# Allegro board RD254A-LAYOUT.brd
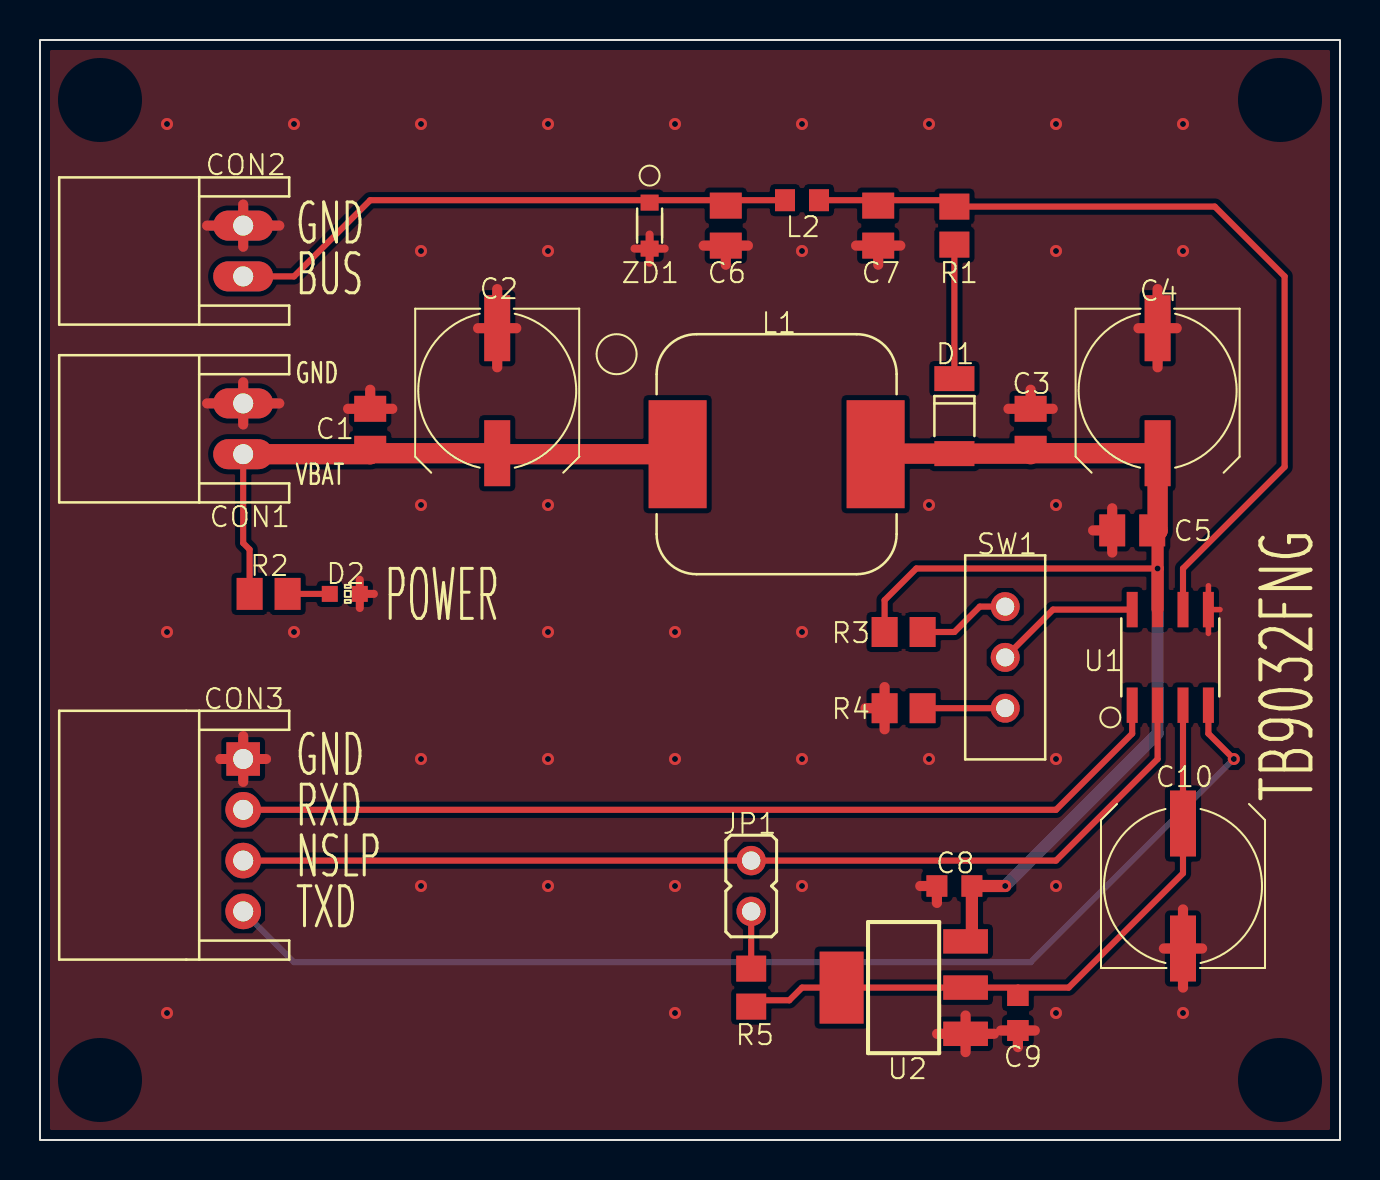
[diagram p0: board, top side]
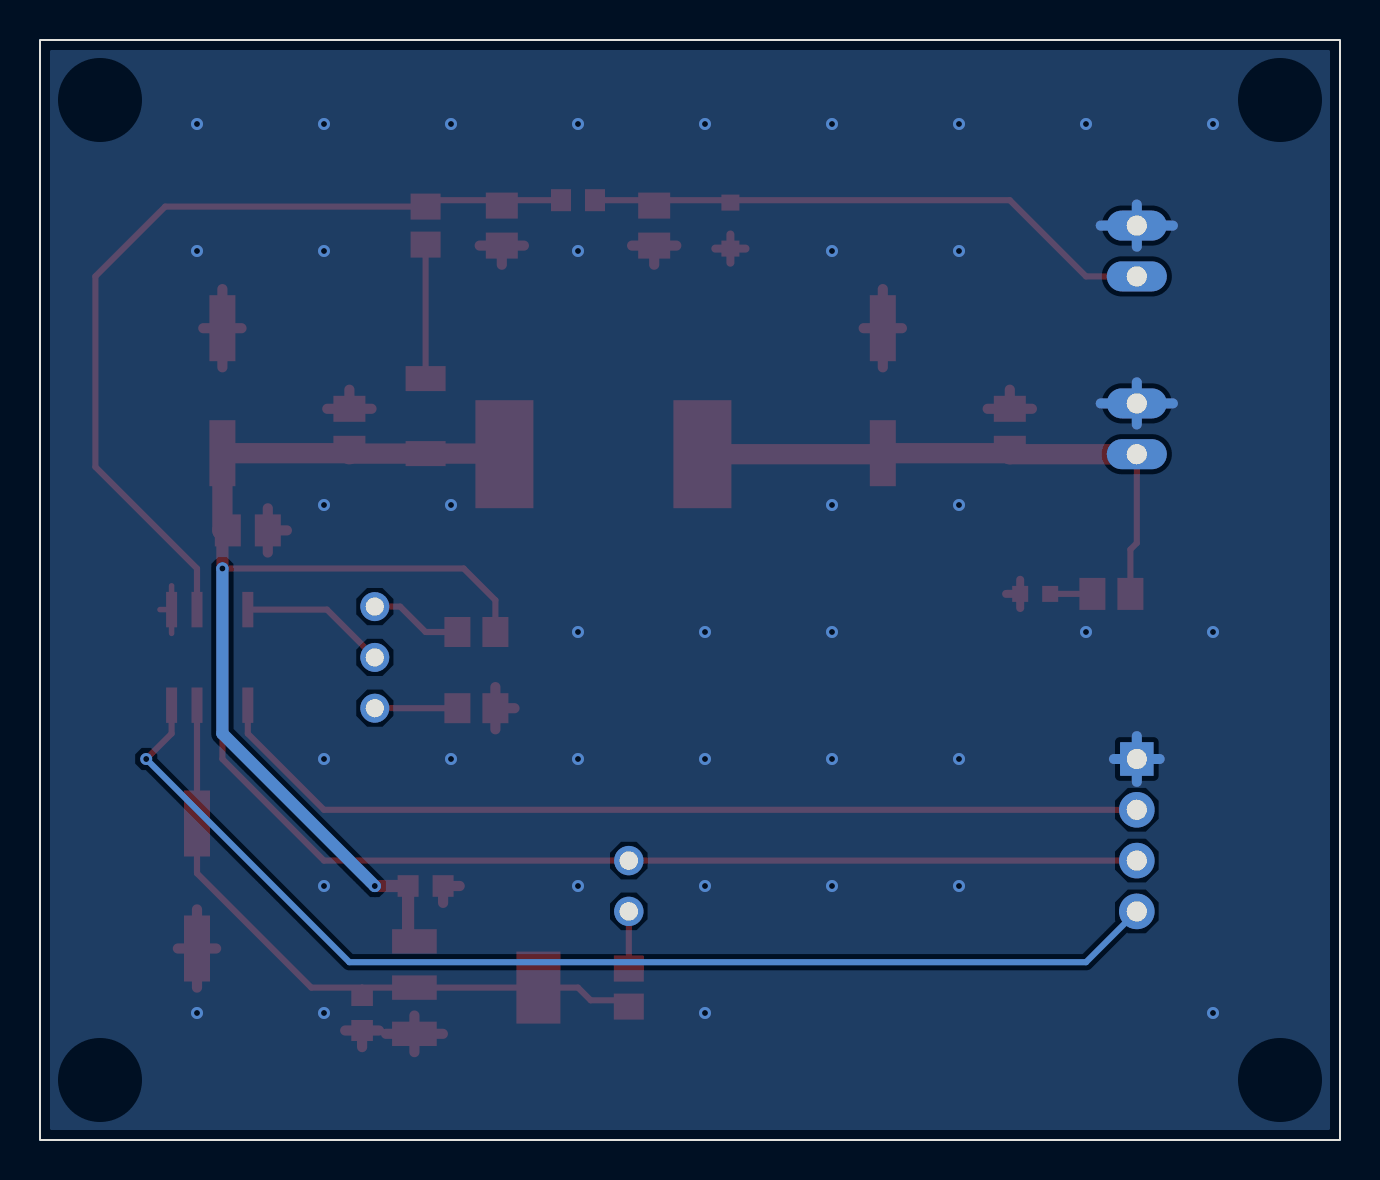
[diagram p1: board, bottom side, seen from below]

Outline 65 x 55 mm; copper layers: TOP, BOTTOM. Coordinates in mm from the lower left corner of the outline.
Outline path: rectangle 0,0 65,55

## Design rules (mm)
constraint set DEFAULT: 

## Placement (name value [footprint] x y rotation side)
C1  -  [C0805K]  16.51 35.56 90 top
C2  -  [UD_8X10_NICHICON_01]  22.86 37.47 270 top
C3  -  [C0805K]  49.53 35.56 90 top
C4  -  [UD_8X10_NICHICON_01]  55.88 37.47 270 top
C5  -  [C0805K]  54.61 30.48 180 top
C6  -  [C0805K]  34.29 45.72 270 top
C7  -  [C0805K]  41.91 45.72 270 top
C8  -  [C0603K]  45.72 12.7 0 top
C9  -  [C0603K]  48.9 6.35 90 top
C10  -  [UD_8X10_NICHICON_01]  57.15 12.7 90 top
CON1  -  [S2B_XH_A]  10.16 35.56 90 top
CON2  -  [S2B_XH_A]  10.16 44.45 90 top
CON3  -  [S4B_XH_A]  10.16 15.24 90 top
D1  -  [LL4148]  45.72 36.2 90 top
D2  -  [CHIP_LED0603]  15.24 27.3 270 top
JP1  -  [JP1]  35.56 12.7 0 top
L1  -  [7447709222]  36.83 34.29 270 top
L2  -  [R0603]  38.1 46.99 0 top
NOREF  -  []  -88 -69 0 top
R1  -  [R0805]  45.72 45.72 270 top
R2  -  [M0805]  11.43 27.3 180 top
R3  -  [R0805]  43.18 25.4 0 top
R4  -  [R0805]  43.18 21.59 180 top
R5  -  [R0805]  35.56 7.62 90 top
SW1  -  [SS_12SDP2]  48.26 24.13 0 top
U1  -  [P_SOP8_0405_1_27_002]  56.52 24.13 90 top
U2  -  [SOT223]  43.18 7.62 90 top
ZD1  -  [USC]  30.48 45.72 270 top

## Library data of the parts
C1 C3 C5-C7 = C0805K: alternate symbols: (T:C0805K,C1_C0805K,C3_C0805K,C5_C0805K,C6_C0805K,C7_C0805K;B:C0805K_bk)
C2 C4 C10 = UD-8X10_NICHICON_01: alternate symbols: (T:UD_8X10_NICHICON_01,C2_UD_8X10_NICHICON_01,C4_UD_8X10_NICHICON_01,C10_UD_8X10_NICHICON_01;B:UD_8X10_NICHICON_01_bk)
C8 C9 = C0603K: alternate symbols: (T:C0603K,C8_C0603K,C9_C0603K;B:C0603K_bk)
CON1 CON2 = S2B-XH-A: alternate symbols: (T:S2B_XH_A,CON1_S2B_XH_A,CON2_S2B_XH_A;B:S2B_XH_A_bk)
CON3 = S4B-XH-A: alternate symbols: (T:S4B_XH_A;B:S4B_XH_A_bk)
D1 = LL4148: alternate symbols: (T:LL4148;B:LL4148_bk)
D2 = CHIP-LED0603: alternate symbols: (T:CHIP_LED0603,D2_CHIP_LED0603;B:CHIP_LED0603_bk)
JP1 = JP1: alternate symbols: (T:JP1,JP1_JP1;B:JP1_bk)
L1 = 7447709222: alternate symbols: (T:7447709222;B:7447709222_bk)
L2 = R0603: alternate symbols: (T:R0603,L2_R0603;B:R0603_bk)
R1 R3-R5 = R0805: alternate symbols: (T:R0805,R1_R0805,R3_R0805,R4_R0805,R5_R0805;B:R0805_bk)
R2 = M0805: alternate symbols: (T:M0805,R2_M0805;B:M0805_bk)
SW1 = SS-12SDP2: alternate symbols: (T:SS_12SDP2;B:SS_12SDP2_bk)
U1 = P-SOP8-0405-1_27-002: alternate symbols: (T:P_SOP8_0405_1_27_002,U1_P_SOP8_0405_1_27_002;B:P_SOP8_0405_1_27_002_bk)
U2 = SOT223: alternate symbols: (T:SOT223,U2_SOT223;B:SOT223_bk)
ZD1 = USC: alternate symbols: (T:USC,ZD1_USC;B:USC_bk)

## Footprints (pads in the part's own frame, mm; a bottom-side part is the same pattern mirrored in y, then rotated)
7447709222
  rect 5.4x2.9 smd: 1(0,-4.95) 2(0,4.95)
C0603K
  rect 1.05x1.08 smd: 1(-0.875,0) 2(0.875,0)
C0805K
  rect 1.3x1.6 smd: 1(-1,0) 2(1,0)
CHIP_LED0603
  rect 0.8x0.8 smd: A(0,-0.75) C(0,0.75)
JP1
  round 1.47 hole 0.914: 1(0,-1.27) 2(0,1.27)
LL4148
  rect 1.25x2 smd: A(-1.875,0) K(1.875,0)
M0805
  rect 1.3x1.6 smd: 1(-0.95,0) 2(0.95,0)
P_SOP8_0405_1_27_002
  rect 1.77x0.55 smd: 1(-2.39,1.905) 2(-2.39,0.635) 3(-2.39,-0.635) 4(-2.39,-1.905) 5(2.39,-1.905) 6(2.39,-0.635) 7(2.39,0.635) 8(2.39,1.905)
R0603
  rect 1x1.1 smd: 1(-0.85,0) 2(0.85,0)
R0805
  rect 1.3x1.5 smd: 1(-0.95,0) 2(0.95,0)
S2B_XH_A
  oval 1.5x3 hole 1: 1(1.27,0) 2(-1.27,0)
S4B_XH_A
  rect 1.676x1.676 hole 1: 1(3.81,0)
  round 1.78 hole 1: 2(1.27,0) 3(-1.27,0) 4(-3.81,0)
SOT223
  rect 1.219x2.235 smd: 1(-2.311,-3.099) 2(0,-3.099) 3(2.311,-3.099)
  rect 3.6x2.2 smd: TAB(0,3.099)
SS_12SDP2
  round 1.45 hole 0.9: 1(0,2.54) 2(0,0) 3(0,-2.54)
UD_8X10_NICHICON_01
  rect 3.3x1.3 smd: 1(-3.125,0) 2(3.125,0)
USC
  rect 0.8x0.9 smd: 1(-1.15,0) 2(1.15,0)

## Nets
+5V: C9.2 C10.2 R5.1 U1.3 U2.2 U2.TAB
+12V: C1.1 C2.2 CON1.2 L1.1 R2.2
GND: C1.2 C2.1 C3.2 C4.1 C5.2 C6.2 C7.2 C8.1 C9.1 C10.1 CON1.1 CON2.1 CON3.1 D2.C R4.2 U1.5 U2.1 ZD1.2
BUS: C3.1 C4.2 C5.1 C6.1 C7.1 C8.2 CON2.2 D1.A D1.K L1.2 L2.1 L2.2 R1.1 R1.2 R3.1 R3.2 SW1.1 U1.6 U1.7 U2.3 ZD1.1
N_2: SW1.2 U1.8
N_15: R4.1 SW1.3
N_30: D2.A R2.1
NSLP: CON3.3 JP1.1 JP1.2 R5.2 U1.2
RXD: CON3.2 U1.1
TXD: CON3.4 U1.4

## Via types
v1: diameter 0.6, hole 0.3, TOP to BOTTOM, 41 vias

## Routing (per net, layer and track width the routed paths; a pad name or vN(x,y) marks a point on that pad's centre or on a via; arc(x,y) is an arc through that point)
+5V: length 33.2
  TOP w0.305: R5.1 35.88,6.99 37.47,6.99 38.1,7.62 U2.TAB U2.2 48.9,7.62 ; U1.3 C10.2 57.15,13.34 51.44,7.62 48.9,7.62 ; 48.9,7.62 C9.2
+12V: length 29.2
  TOP w0.305: R2.2 10.48,29.52 10.16,29.84 CON1.2
  TOP w1.016: CON1.2 16.51,34.29 16.51,34.34 ; 16.51,34.34 C2.2 22.86,34.29 L1.1 ; 16.51,34.34 C1.1
GND: length 85.2
  TOP w0.275: 58.42,25.33 U1.5 ; U1.5 58.42,27.71 ; U1.5 59,26.52
  TOP w0.4: D2.C 16.7,27.3 ; D2.C 15.99,28.01 ; D2.C 15.99,26.6 ; 29.73,44.57 ZD1.2 ; ZD1.2 31.23,44.57 ; ZD1.2 30.48,43.87 ; ZD1.2 30.48,45.27
  TOP w0.5: CON1.1 11.96,36.83 ; CON1.1 10.16,35.77 ; CON1.1 10.16,37.88 ; CON1.1 8.36,36.83 ; 10.16,17.91 CON3.1 ; CON3.1 10.16,20.19 ; CON3.1 9.02,19.05 ; CON3.1 11.3,19.05 ; 10.16,44.66 CON2.1 ; CON2.1 10.16,46.77 ; CON2.1 8.36,45.72 ; CON2.1 11.96,45.72
  TOP w0.508: U2.1 47.7,5.31 ; U2.1 46.28,6.22 ; U2.1 44.86,5.31 ; U2.1 46.28,4.39 ; C6.2 35.4,44.72 ; C6.2 34.29,43.77 ; C6.2 33.19,44.72 ; 55.88,38.63 C4.1 ; C4.1 54.92,40.59 ; C4.1 56.84,40.59 ; C4.1 55.88,42.55 ; 40.8,44.72 C7.2 ; C7.2 41.91,43.77 ; C7.2 43.02,44.72 ; C10.1 57.15,11.53 ; C10.1 58.1,9.57 ; C10.1 56.2,9.57 ; C10.1 57.15,7.62 ; 48.9,4.64 C9.1 ; C9.1 49.74,5.47 ; C9.1 48.05,5.47 ; 53.61,29.38 C5.2 ; C5.2 53.61,31.59 ; C5.2 52.66,30.48 ; 15.4,36.56 C1.2 ; C1.2 16.51,37.52 ; C1.2 17.61,36.56 ; 48.42,36.56 C3.2 ; C3.2 49.53,37.52 ; C3.2 50.63,36.56 ; R4.2 42.23,22.64 ; R4.2 41.27,21.59 ; R4.2 42.23,20.54 ; 22.86,38.63 C2.1 ; C2.1 21.91,40.59 ; C2.1 22.86,42.55 ; C2.1 23.82,40.59 ; 44.02,12.7 C8.1 44.84,11.86
  BOTTOM w0.5: CON1.1 10.16,37.88 ; CON1.1 10.16,35.77 ; CON1.1 8.36,36.83 ; CON1.1 11.96,36.83 ; 10.16,44.66 CON2.1 ; CON2.1 11.96,45.72 ; CON2.1 8.36,45.72 ; CON2.1 10.16,46.77 ; 9.02,19.05 CON3.1 ; CON3.1 11.3,19.05 ; CON3.1 10.16,17.91 ; CON3.1 10.16,20.19
  vias: v1(6.35,50.8) v1(6.35,25.4) v1(6.35,6.35) v1(12.7,50.8) v1(12.7,25.4) v1(19.05,50.8) v1(19.05,44.45) v1(19.05,31.75) v1(19.05,19.05) v1(19.05,12.7) v1(25.4,50.8) v1(25.4,44.45) v1(25.4,31.75) v1(25.4,25.4) v1(25.4,19.05) v1(25.4,12.7) v1(31.75,50.8) v1(31.75,25.4) v1(31.75,19.05) v1(31.75,12.7) v1(31.75,6.35) v1(38.1,50.8) v1(38.1,44.45) v1(38.1,25.4) v1(38.1,19.05) v1(38.1,12.7) v1(44.45,50.8) v1(44.45,31.75) v1(44.45,19.05) v1(50.8,50.8) v1(50.8,44.45) v1(50.8,31.75) v1(50.8,19.05) v1(50.8,12.7) v1(50.8,6.35) v1(57.15,50.8) v1(57.15,44.45) v1(57.15,6.35)
BUS: length 146.6
  TOP w0.305: CON2.2 12.7,43.18 16.51,46.99 30.36,46.99 ZD1.1 30.48,46.99 34.29,46.99 ; SW1.1 46.99,26.67 45.72,25.4 R3.2 ; R3.1 42.23,26.99 43.81,28.57 v1(55.88,28.57) ; 41.91,46.99 45.72,46.99 R1.1 58.74,46.67 62.23,43.18 62.23,33.66 57.15,28.57 U1.6 ; 41.91,46.99 C7.1 ; 41.91,46.99 L2.2 ; R1.2 D1.K ; 34.29,46.99 C6.1 ; 34.29,46.99 L2.1
  TOP w0.61: U2.3 46.59,10.25 C8.2 v1(48.26,12.7) ; C5.1 55.88,30.21 v1(55.88,28.57) U1.7
  TOP w1.016: L1.2 41.78,34.32 D1.A 49.53,34.32 ; C3.1 49.53,34.34 ; 49.53,34.34 C4.2 55.88,30.48 C5.1 ; 49.53,34.34 49.53,34.32 ; 49.53,34.32 49.53,34.29
  BOTTOM w0.61: v1(48.26,12.7) 55.88,20.32 v1(55.88,28.57)
N_2: length 7.3
  TOP w0.305: U1.8 50.65,26.52 SW1.2
N_15: length 4.1
  TOP w0.305: R4.1 SW1.3
N_30: length 2.1
  TOP w0.305: R2.1 D2.A
NSLP: length 53.4
  TOP w0.305: CON3.3 JP1.2 50.8,13.97 55.88,19.05 U1.2 ; JP1.1 R5.2
RXD: length 47.4
  TOP w0.305: U1.1 54.61,20.32 50.8,16.51 CON3.2
TXD: length 58
  TOP w0.305: U1.4 58.42,20.32 v1(59.69,19.05)
  BOTTOM w0.305: CON3.4 12.7,8.89 49.53,8.89 v1(59.69,19.05)

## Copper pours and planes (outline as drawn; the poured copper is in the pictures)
GND on TOP: 64.5,0.57 64.48,0.52 64.43,0.5 0.57,0.5 0.52,0.52 0.5,0.57 0.5,54.43 0.52,54.48 0.57,54.5 64.43,54.5 64.48,54.48 64.5,54.43 ; 17 cut-outs
GND on BOTTOM: 64.5,0.57 64.48,0.52 64.43,0.5 0.57,0.5 0.52,0.52 0.5,0.57 0.5,54.43 0.52,54.48 0.57,54.5 64.43,54.5 64.48,54.48 64.5,54.43 ; 18 cut-outs

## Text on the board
Ref Des/Silkscreen Top: GND | VBAT | CON3 | CON2 | CON1 | R2 | C1 | D2 | C2 | ZD1 | C6 | JP1 | R5 | L1 | L2 | R3 | R4 | C7 | U2 | D1 | C8 | R1 | SW1 | C9 | C3 | U1 | C4 | C10 | C5 | BUS | RXD | NSLP | TXD | POWER | TB9032FNG
SYMBOL-1-TOP: VALUE
SYMBOL-2-TOP: VALUE
